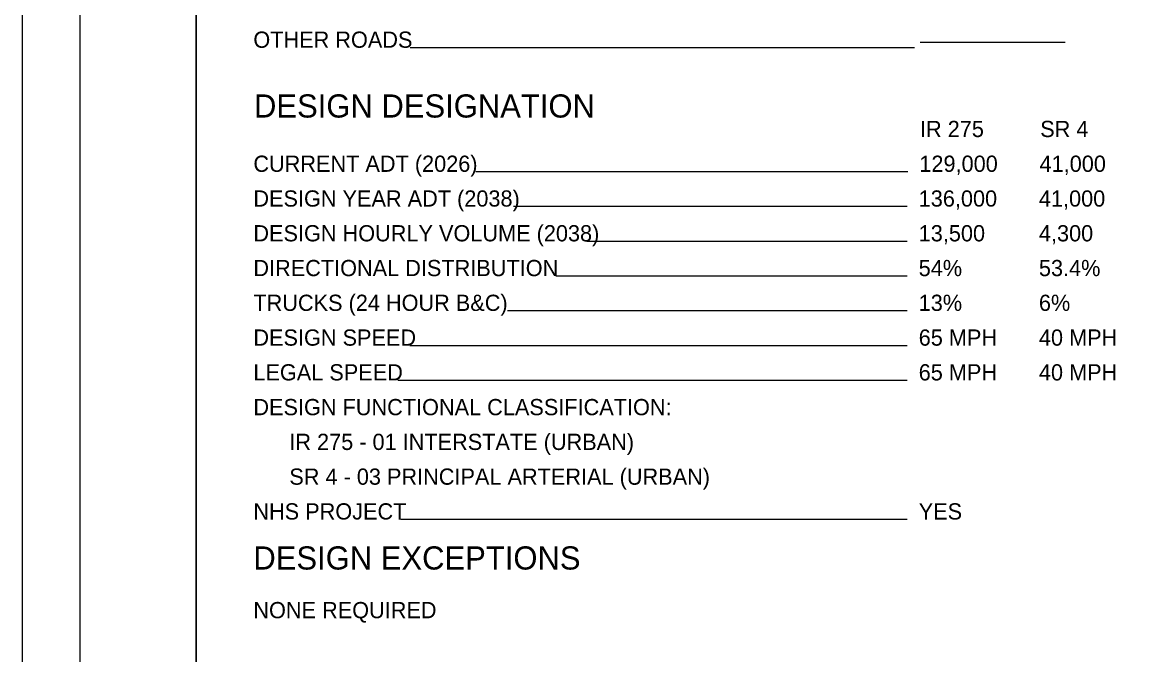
# Model space of a CAD drawing. Extents: x 0 to 34, y -6.8 to 22.
# Drawn here: x 0 to 9.62, y 5.64 to 11.1 of the extents above; entities that cross this region are included whole.
import ezdxf

# ---------------------------------------------------------------- set-up
doc = ezdxf.new("R2010")
doc.units = 0
for name, color, linetype in [('GM_X_County', 7, 'Continuous'), ('GM_X_Minor_Lake', 7, 'Continuous'), ('GM_X_Minor_Lake_Text', 7, 'Continuous'), ('GM_X_Minor_River_Text', 7, 'Continuous')]:
    doc.layers.add(name, color=color, linetype=linetype)

msp = doc.modelspace()

# ---------------------------------------------------------------- linework, layer by layer
at = {"layer": 'GM_X_County'}
msp.add_lwpolyline([(0, 0), (34, 0), (34, 22), (0, 22)], close=True, dxfattribs=at)
at = {"layer": 'GM_X_Minor_Lake_Text'}
for p, q in [((7.7, 10.8767), (3.3471, 10.8767)), ((9, 10.9223), (7.75, 10.9223)), ((7.6424, 9.8062), (3.9155, 9.8062)), ((7.6368, 9.5062), (4.2409, 9.5062)), ((7.6368, 9.2062), (4.8723, 9.2062)), ((7.6368, 8.9062), (4.6037, 8.9062)), ((7.6368, 8.6062), (4.1885, 8.6062)), ((7.6368, 8.3062), (3.346, 8.3062)), ((7.6368, 8.0062), (3.2422, 8.0062)), ((7.6368, 6.8062), (3.2669, 6.8062))]:
    msp.add_line(p, q, dxfattribs=at)
at = {"layer": 'GM_X_Minor_River_Text'}
for points in [[(0.5, 21.5), (1.5, 21.5), (1.5, 0.5), (0.5, 0.5)], [(1.5, 21.5), (33.5, 21.5), (33.5, 0.5), (1.5, 0.5)]]:
    msp.add_lwpolyline(points, close=True, dxfattribs=at)

# ---------------------------------------------------------------- texts
at = {"layer": 'GM_X_Minor_Lake'}
for s, height, p in [('OTHER ROADS', 0.14, (1.9944, 10.8767)), ('IR 275', 0.14, (7.748, 10.1062)), ('SR 4', 0.14, (8.7855, 10.1062)), ('CURRENT ADT (2026) ', 0.14, (1.9944, 9.8062)), ('129,000', 0.14, (7.7424, 9.8062)), ('41,000', 0.14, (8.7799, 9.8062)), ('DESIGN YEAR ADT (2038)', 0.14, (1.9944, 9.5062)), ('136,000', 0.14, (7.7368, 9.5062)), ('41,000', 0.14, (8.7743, 9.5062)), ('DESIGN HOURLY VOLUME (2038)', 0.14, (1.9944, 9.2062)), ('13,500', 0.14, (7.7368, 9.2062)), ('4,300', 0.14, (8.7743, 9.2062)), ('DIRECTIONAL DISTRIBUTION', 0.14, (1.9944, 8.9062)), ('54%', 0.14, (7.7368, 8.9062)), ('53.4%', 0.14, (8.7743, 8.9062)), ('TRUCKS (24 HOUR B&C)', 0.14, (1.9944, 8.6062)), ('13%', 0.14, (7.7368, 8.6062)), ('6%', 0.14, (8.7743, 8.6062)), ('DESIGN SPEED', 0.14, (1.9944, 8.3062)), ('65 MPH', 0.14, (7.7368, 8.3062)), ('40 MPH', 0.14, (8.7743, 8.3062)), ('LEGAL SPEED', 0.14, (1.9944, 8.0062)), ('65 MPH', 0.14, (7.7368, 8.0062)), ('40 MPH', 0.14, (8.7743, 8.0062)), ('DESIGN FUNCTIONAL CLASSIFICATION:', 0.14, (1.9944, 7.7062)), ('IR 275 - 01 INTERSTATE (URBAN)', 0.14, (2.3048, 7.4062)), ('SR 4 - 03 PRINCIPAL ARTERIAL (URBAN)', 0.14, (2.3048, 7.1062)), ('NHS PROJECT', 0.14, (1.9944, 6.8062)), ('YES', 0.14, (7.7368, 6.8062)), ('DESIGN EXCEPTIONS', 0.2, (1.9944, 6.3744)), ('NONE REQUIRED', 0.14, (1.9944, 5.9544))]:
    msp.add_text(s, height=height, dxfattribs=at).set_placement(p)
at = {"layer": 'GM_X_Minor_Lake_Text'}
msp.add_text('DESIGN DESIGNATION', height=0.2, dxfattribs=at).set_placement((2, 10.2747))

doc.saveas('drawing.dxf')
